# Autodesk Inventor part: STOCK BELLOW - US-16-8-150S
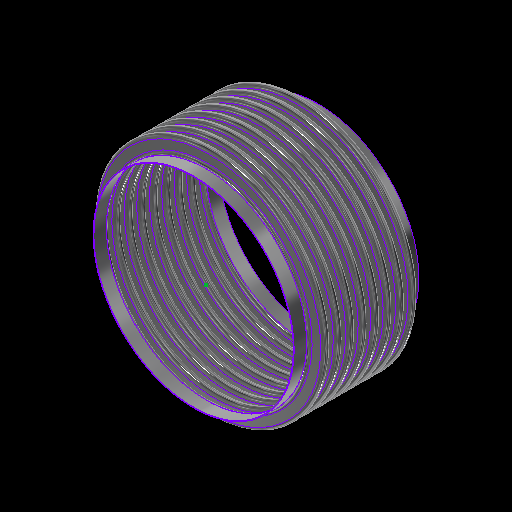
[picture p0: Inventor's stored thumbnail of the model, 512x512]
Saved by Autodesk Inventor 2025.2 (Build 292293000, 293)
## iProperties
Category: 16 GA (0.060 THICK)
RuleStatus: InUse
Created: 2024-01
Part Number: STOCK BELLOW - US-16-8-150S
Project: =STOCK BELLOWS: <Stock Number><SFILL>
Material: ASTM A240-304
Description: =STOCK BELLOWS: <Stock Number>, <SID_> I.D., <SOD_> O.D., <SPLY_> PLY, <Category>, <SNET_CONS> CONS.<PITCH_><STANGENT_> TANGENT<SFILL>
Document SubType Name: Sheet Metal
Designer: GS
Stock Number: U.S-16-8-150S
Surface Area: 17926.1 cm^2
Volume: 1357.04 cm^3
Sheet Metal Rule: Default
Appearance: STAINLESS STEEL
Mass: 10934.1 g
Density: 8.05729 g/cm^3
THK: 0.036
ID: 3.500
OD: 4.250
CONS_: 2
PITCH: 0.500
TANGENT: 0.500
BELLOWS_UPSET: 0.000
d79: 1.000
d82: 1.000
d83: 26.000
d84: 24.000
d174: 8
d214: 8
STHK_: 0.060
SID_: 16.000
SOD_: 18.500
SPITCH_: 1.000
STANGENT__: 1.000
SBELLOWS_UPSET_: 0.000
SDIFF_TAN: 1.000
d252: 2
d275: 2
d287: 0.050
d289: 0.500
d290: 0.000
SOD_NECK: 16 1/8
PLY: 1
PSET: 4.178
PBAR: 1.035
COUNTER: 1.500
NET_TUBE: 3.071
CONS: 2
S_CONS: 0
NET_CONS: 2
ID_M: 88.90 mm
OD_M: 107.95 mm
THK_M: 0.91 mm
ID_U: 3.500 in
OD_U: 4.250 in
THK_U: 0.036 in
TANGENT2: 0.500
TAN_TO_TAN: 1.000 in
d80: 2.571
d81: 10
SID: 2.375
SCONS_: 8
SPITCH: 0.250
STANGENT_: 1.000
SBELLOWS_UPSET: 0.000
SNET_CONS: 8
SS_CONS: 0
SCONS: 8
d190: 8
d191: 1
d192: 1
d193: 8
d194: 0
SIZE: 16.00
PRESSURE: 150
d230: 8
STANGENT: 4.000
SPLY_: 1
d233: 8
d234: 0
d263: 2
d265: 1
d268: 2
d269: 0
d286: 2
d288: 1
d291: 2
d292: 0
SREROLL: 0.750
BLETP: 0.000 ul
PRES_Copy: 85
MATTABLE: 20 GA (0.036 THICK)
PART_NUMBER: U.S-16-8-150S
PITCH_: =, <SPITCH_> PITCH,
CFILL: .
SFILL: .
MESH: ,
COMP: 1.52
EXT: 0.76
LAT: 0.23
ANG: 573
ASR: 4473
LSR: 28074
ANSR: 2613
PRES: 150
COMPM: 15.2
EXTM: 7.6
LATM: 2.30
ASRM: 783.356
PRESM: 10.342
LSRM: 4916.600
ANSRM: 457.615
TEMPMIN: 20
TEMPMAX: 800
TEMPMINM: -7
TEMPMAXM: 427
WEIGHTM: 10.934
WEIGHT: 24.105
Author: GS
Keywords: 20 GA (0.036 THICK)
Comments: =STOCK BELLOW - <STOCK NUMBER>
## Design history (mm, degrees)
sketch "Sketch2"
  geometry: L1 (0, -177.245)-(0, 562.856) reference; L2 (45.364, 0)-(44.45, 0); L3 (48.082, -2.718)-(50.343, -2.718); L4 (48.082, -3.632)-(50.343, -3.632); L5 (50.343, -9.982)-(48.082, -9.982); L6 (50.343, -9.068)-(48.082, -9.068); L7 (45.364, -12.7)-(44.45, -12.7); L8 (48.082, 0)-(48.082, -12.7); L9 (50.343, -6.35)-(53.975, -6.35); L10 (44.45, 0)-(44.45, -12.7); L11 (20.376, 102.841)-(20.376, 101.926); L12 (58.262, 457.127)-(58.262, 349.177); L13 (58.262, 444.427)-(58.262, 336.477); L14 (93.133, -58.817)-(93.133, -71.517); L15 (118.746, -66.401)-(118.746, -66.401); L16 (50.343, -9.068)-(50.343, -9.982); L17 (48.082, -9.068)-(48.082, -9.982); L18 (48.082, -9.525)-(50.343, -9.525); L19 (53.975, 0)-(53.975, -12.7); L20 (-50.343, -9.068)-(-50.343, -9.982); L21 (-50.343, -2.718)-(-48.082, -2.718); L22 (-50.343, -3.632)-(-48.082, -3.632); L23 (-48.082, -9.068)-(-50.343, -9.068); L24 (-50.343, -9.525)-(-48.082, -9.525); L25 (-48.082, -9.982)-(-50.343, -9.982); L26 (-48.082, -9.068)-(-48.082, -9.982); L27 (-44.45, 0.653)-(-44.45, -12.047); L28 (-48.082, -6.35)-(-44.45, -6.35); L29 (-50.343, 0.653)-(-50.343, -12.7); L30 (-53.061, 0)-(-53.975, 0); L31 (-53.975, 0)-(-53.975, -12.7); L32 (-53.061, -12.7)-(-53.975, -12.7); A1 r 2.718 centre (48.082, 0) between (45.364, 0) and (48.082, -2.718); A2 r 3.632 centre (48.082, 0) between (44.45, 0) and (48.082, -3.632); A3 r 3.632 centre (50.343, -6.35) between (50.343, -9.982) and (50.343, -2.718); A4 r 2.718 centre (50.343, -6.35) between (50.343, -9.068) and (50.343, -3.632); A5 r 2.718 centre (48.082, -12.7) between (48.082, -9.982) and (45.364, -12.7); A6 r 3.632 centre (48.082, -12.7) between (48.082, -9.068) and (44.45, -12.7); A7 r 3.175 centre (50.343, -6.35) between (50.343, -9.525) and (53.518, -6.35); A8 r 3.175 centre (48.082, -12.7) between (48.082, -9.525) and (44.907, -12.7); A9 r 2.718 centre (-50.343, -12.7) between (-50.343, -9.982) and (-53.061, -12.7); A10 r 2.718 centre (-48.082, -6.35) between (-48.082, -9.068) and (-48.082, -3.632); A11 r 3.175 centre (-48.082, -6.35) between (-48.082, -9.525) and (-44.907, -6.35); A12 r 3.632 centre (-48.082, -6.35) between (-48.082, -9.982) and (-48.082, -2.718); A13 r 3.175 centre (-50.343, -12.7) between (-50.343, -9.525) and (-53.518, -12.7); A14 r 3.632 centre (-50.343, -12.7) between (-50.343, -9.068) and (-53.975, -12.7); A15 r 2.718 centre (-50.343, 0) between (-53.061, 0) and (-50.343, -2.718); A16 r 3.632 centre (-50.343, 0) between (-53.975, 0) and (-50.343, -3.632); 10 further points
  constraints: 62 end point, 38 point on circle, 20 tangent, 16 centre point, 12 parallel, 9 midpoint, 7 vertical, 6 coincident, 6 concentric, 6 point on line, 4 equal radius, 4 perpendicular, 3 horizontal, 1 collinear, 1 horizontal alignment, 10 other
  dimensions: "THK" = 0.9144 distance of L11.start L11.end; "ID" = 88.9 distance of L11.end point (20.376, 13.026); "OD" = 107.95 distance of L12.start L12.end; "PITCH" = 12.7 distance of L12.start L13.start; "TANGENT" = 12.7 distance of L14.start L14.end; "BELLOWS_UPSET" = 0 distance of L15.start L15.end; "d43" = 88.9 diameter of L10 L1 (= ID); "d44" = 107.95 diameter of L9.end L1 (= OD); "d45" = 0.9144 distance between parallel lines of L5 L6 (computed from THK, PLY); "d46" = 3.6322 radius of A3 (computed from PITCH, THK, PLY); "UPSET_PITCH" = 12.7 distance of L2.end L7.end (derived); "SIDEWALL_ANGLE" = 360 deg dimension on L3 L9 (derived); "CON_GAP" = 5.4356 distance of point (48.082, -9.068) point (48.082, -3.632) (derived); "TAN1" = 4.98728 dimension on A8 (derived); "TAN2" = 4.98728 dimension on A7 (derived); "LEG1" = 2.2606 distance of L18.start L18.end (derived); "d278" = 0.9144 distance between parallel lines of L25 L23 (derived); "d279" = 3.6322 radius of A12 (derived); "d280" = 12.7 distance of L30.end L31.end (derived); "d281" = 360 deg dimension on L21 L28 (derived); "d282" = 5.4356 distance of point (-50.343, -9.068) point (-50.343, -3.632) (derived); "d283" = 4.98728 dimension on A13 (derived); "d284" = 4.98728 dimension on A11 (derived); "d285" = 2.2606 distance of L24.start L24.end (derived); "d293" = 88.9 diameter of L27 L1 (derived); "d294" = 107.95 diameter of L31 L1 (derived)
  node "Sketch Rectangular Pattern1" dims "d31" = 25.4, "ID" = 88.9
  node "Sketch Rectangular Pattern2" dims "d39" = 25.4, "PITCH" = 12.7
revolve "CONS" stored, may be unused: angle "d48" = 90 deg
node "BELLOW MIDPLANE"
pattern_linear "Rectangular Pattern2" dims "d52" = 12.7 (= UPSET_PITCH)
sketch "Sketch5"
  geometry: C1 r 45.364 at (0, 0) reference; C2 r 44.45 at (0, 0) reference
extrude "TANGENT" new body sketch "Sketch5" distance "d53" = 12.7 (= TANGENT); taper "d54" = 0 deg
revolve "SAMETAN" stored, may be unused: angle "d65" = 90 deg
revolve "DIFFTAN" stored, may be unused: angle "d70" = 90 deg
sketch "Sketch9"
  geometry: L1 (53.319, 0)-(-53.319, 0) reference; L2 (0, -17.78)-(0, 17.78) reference; L3 (38.085, 0)-(-38.085, 0); L4 (38.085, -11.906)-(38.085, 11.906); L5 (25.385, -11.906)-(25.385, 11.906); L6 (13.15, 11.906)-(13.15, -11.906); L7 (-25.385, -11.906)-(-25.385, 11.906); L8 (-38.085, -11.906)-(-38.085, 11.906); L9 (37.291, -11.906)-(37.291, 11.906); L10 (38.085, -11.906)-(37.291, -11.906); L11 (38.085, 11.906)-(37.291, 11.906); L12 (13.546, 11.906)-(12.753, 11.906); L13 (12.753, 11.906)-(12.753, -11.906); L14 (12.753, -11.906)-(13.546, -11.906); L15 (13.546, -11.906)-(13.546, 11.906); L16 (-13.546, 11.906)-(-13.546, -11.906); L17 (-13.15, 11.906)-(-13.15, -11.906); L18 (-13.546, -11.906)-(-12.753, -11.906); L19 (-12.753, -11.906)-(-12.753, 11.906); L20 (-12.753, 11.906)-(-13.546, 11.906); L21 (-38.085, -11.906)-(-37.291, -11.906); L22 (-37.291, -11.906)-(-37.291, 11.906); L23 (-37.291, 11.906)-(-38.085, 11.906); L24 (-38.085, 11.906)-(-38.085, -11.906); L25 (38.085, -0.397)-(-38.085, -0.397); L26 (-38.085, -0.397)-(-38.085, 0.397); L27 (-38.085, 0.397)-(38.085, 0.397); L28 (38.085, 0.397)-(38.085, -0.397); L29 (-38.085, 11.906)-(38.085, 11.906); L30 (38.085, 11.906)-(38.085, 12.7); L31 (38.085, 12.7)-(-38.085, 12.7); L32 (-38.085, 12.7)-(-38.085, 11.906); L33 (38.085, -11.906)-(-38.085, -11.906); L34 (-38.085, -11.906)-(-38.085, -12.7); L35 (-38.085, -12.7)-(38.085, -12.7); L36 (38.085, -12.7)-(38.085, -11.906); 30 further points
  constraints: 68 end point, 13 midpoint, 13 parallel, 8 horizontal, 7 perpendicular, 6 equal length, 3 point on line, 2 vertical, 14 other
  dimensions: "d115" = 23.8125 distance of L4.start L4.end (derived); "d116" = 12.7 distance between parallel lines of L4 L5 (derived); "d117" = 12.23516 distance between parallel lines of L5 L6 (derived); "d125" = 38.53427 distance between parallel lines of L7 L6 (derived); "d127" = 12.7 distance between parallel lines of L8 L7 (derived); "d128" = 24.93516 distance between parallel lines of L6 L4 (derived); "d130" = 76.16943 distance between parallel lines of L8 L4 (derived); "RULER_THK" = 0.79375 distance between parallel lines of L4 L9; "d135" = 0.79375 distance of L13.end L14.end (derived); "d138" = 26.29911 distance of L13.end L16.end (derived); "d143" = 0.79375 distance of L22.end L8.end (derived); "d144" = 0.79375 distance between parallel lines of L27 L25 (derived)
extrude "RULER" join sketch "Sketch9" distance "d149" = 0.79375 (derived); taper "d150" = 0 deg
extrude "BARS" join sketch "Sketch9" distance "d151" = 0.79375 (derived); taper "d152" = 0 deg
pattern_linear "Rectangular Pattern4" dims "d155" = 26.29911 (derived)
sketch "Sketch13"
  geometry: L1 (93.149, -52.467)-(93.149, -77.867); L2 (204.724, 0)-(203.2, 0); L3 (204.724, -25.4)-(203.2, -25.4); L4 (227.838, -19.812)-(210.312, -19.812); L5 (227.838, -18.288)-(210.312, -18.288); L6 (227.838, -12.7)-(234.95, -12.7); L7 (210.312, -5.588)-(227.838, -5.588); L8 (210.312, 0)-(210.312, -25.4); L9 (203.2, 0)-(203.2, -25.4); L10 (58.254, -26.531)-(58.254, -496.431); L11 (58.254, -51.931)-(58.254, -521.831); L12 (58.254, -102.731)-(58.254, -572.631); L13 (58.254, -128.131)-(58.254, -598.031); L14 (58.254, -153.531)-(58.254, -623.431); L15 (58.254, -178.931)-(58.254, -648.831); L16 (58.254, -204.331)-(58.254, -674.231); L17 (58.254, -77.331)-(58.254, -547.231); L18 (20.376, 103.45)-(20.376, 101.926); L19 (210.312, -7.112)-(227.838, -7.112); L20 (0, -829.767)-(0, 258.986) reference; L21 (-46.99, 0)-(281.94, 0) reference; A1 r 5.588 centre (210.312, 0) between (204.724, 0) and (210.312, -5.588); A2 r 5.588 centre (210.312, -25.4) between (210.312, -19.812) and (204.724, -25.4); A3 r 7.112 centre (210.312, -25.4) between (210.312, -18.288) and (203.2, -25.4); A4 r 5.588 centre (227.838, -12.7) between (227.838, -18.288) and (227.838, -7.112); A5 r 7.112 centre (227.838, -12.7) between (227.838, -19.812) and (227.838, -5.588); A6 r 7.112 centre (210.312, 0) between (203.2, 0) and (210.312, -7.112); 6 further points; 1 other entity
  constraints: 38 end point, 15 point on circle, 9 tangent, 6 centre point, 6 parallel, 5 vertical alignment, 4 point on line, 4 vertical, 3 coincident, 3 concentric, 2 collinear, 2 equal radius, 1 horizontal, 1 perpendicular, 23 other
  dimensions: "SBELLOWS_UPSET_" = 0 distance of point (118.762, -66.401) point (118.762, -66.401); "STOTAL_THK_BELLOW__" = 1.524 distance between parallel lines of L4 L5 (derived); "d224" = 7.112 radius of A5 (derived); "d225" = 25.4 distance of L2.end L3.end (derived); "SSIDEWALL_ANGLE_" = 360 deg dimension on L7 L6 (derived); "SSCON_GAP_" = 11.176 distance of point (210.312, -18.288) point (210.312, -7.112) (derived); "d235" = 406.4 diameter of L9 L20 (derived); "d236" = 469.9 diameter of L6.end L20 (derived)
  node "Sketch Rectangular Pattern4" dims "d228" = 25.4
  node "Sketch Rectangular Pattern5" dims "d229" = 25.4
revolve "SBELLOW" stored, may be unused: angle "d197" = 90 deg
pattern_linear "Rectangular Pattern5" dims "d204" = 25.4 (derived)
revolve "STANGENT" stored, may be unused: angle "d240" = 90 deg
revolve "SSAMETAN" stored, may be unused: angle "d241" = 90 deg
revolve "SDIFFTAN" stored, may be unused: angle "d246" = 90 deg
revolve "INVCON" stored, may be unused: angle "d295" = 90 deg
pattern_linear "Rectangular Pattern6" dims "d298" = 12.7 (derived)
revolve "INVTANGENT" stored, may be unused: angle "d302" = 90 deg
revolve "INVSAMETAN" stored, may be unused: angle "d307" = 90 deg
revolve "INVDIFFTAN" stored, may be unused: angle "d312" = 90 deg
sketch "ID BELLOW MOUNT CALC"
  geometry: L1 (44.45, 0)-(38.1, 0); L2 (38.1, 0)-(38.1, 12.7); L3 (38.1, 12.7)-(44.45, 12.7); L4 (44.45, 12.7)-(44.45, 0); L5 (36.513, 12.7)-(35.598, 12.7); L6 (35.598, 12.7)-(35.598, 0); L7 (35.598, 0)-(36.513, 0); L8 (36.513, 0)-(36.513, 12.7); L9 (0, -2.54)-(0, 15.24) reference; L10 (-8.89, 0)-(53.34, 0) reference; 1 further point
  constraints: 16 end point, 5 parallel, 2 collinear, 2 horizontal, 2 perpendicular
  dimensions: "d314" = 12.7 distance of L5.end L6.end (derived); "d315" = 0.9144 distance of L5.start L5.end (derived); "IG" = 1.5875 distance between parallel lines of L2 L8; "PIPE_OD" = 88.9 diameter of L4 L9; "PIPE_WALL" = 6.35 distance of L2.end L3.end; "ID_MT_BELLOW" = 71.1962 diameter of L6 L9 (derived)
revolve "CFILL" stored, may be unused: angle "d320" = 90 deg
pattern_linear "Rectangular Pattern7" dims "d323" = 12.7 (derived)
revolve "SFILL" stored, may be unused: angle "d324" = 90 deg
pattern_linear "Rectangular Pattern8" dims "d327" = 25.4 (derived)
node "STOCK BELLOW MIDPLANE"
node "BELLOW"
sketch "Sketch6"
  geometry: L1 (-12.7, 45.364)-(0, 45.364); L2 (0, 45.364)-(0, 44.45); L3 (0, 44.45)-(-12.7, 44.45); L4 (-12.7, 44.45)-(-12.7, 45.364); L5 (10.16, 0)-(-60.96, 0) reference; L6 (-38.1, -89.422)-(-38.1, 153.44) reference; 1 further point
  constraints: 8 end point, 2 parallel, 1 horizontal, 1 perpendicular
  dimensions: "d61" = 12.7 distance of L2.end L3.end (derived); "d62" = 0.9144 distance of L1.end L2.end (derived); "d63" = 88.9 diameter of L3 L5 (derived); "d64" = 25.4 distance between parallel lines of L4 L6 (derived)
sketch "Sketch12"
  geometry: 1 further point
sketch "Sketch14"
  geometry: L1 (-25.4, 204.724)-(0, 204.724); L2 (0, 204.724)-(0, 203.2); L3 (0, 203.2)-(-25.4, 203.2); L4 (-25.4, 203.2)-(-25.4, 204.724); L5 (5.08, 0)-(-30.48, 0) reference; L6 (0, -40.945)-(0, 245.669) reference; 1 further point
  constraints: 8 end point, 2 parallel, 1 collinear, 1 horizontal, 1 perpendicular
  dimensions: "d237" = 1.524 distance of L3.end L1.start (derived); "d238" = 406.4 diameter of L3 L5 (derived); "d239" = 25.4 distance of L1.start L1.end (derived); "SOD_NECK" = 409.448 diameter of L1 L5 (derived)
sketch "Sketch15"
  geometry: L1 (-40.945, 0)-(245.669, 0) reference; L2 (203.2, -203.2)-(204.724, -203.2); L3 (204.724, -203.2)-(204.724, -228.6); L4 (204.724, -228.6)-(203.2, -228.6); L5 (203.2, -228.6)-(203.2, -203.2); L6 (0, -276.86)-(0, 60.96) reference; 1 further point
  constraints: 8 end point, 2 parallel, 1 horizontal, 1 perpendicular
  dimensions: "d205" = 25.4 distance of L4.end L2.start (derived); "d206" = 1.524 distance of L3.end L4.end (derived); "d207" = 406.4 diameter of L5 L6 (derived); "d208" = 203.2 distance between parallel lines of L1 L2 (derived)
node "TANGENT_"
node "SAME_TAN"
sketch "Sketch8"
  geometry: L1 (45.364, -25.4)-(44.45, -25.4); L2 (44.45, -25.4)-(44.45, -38.1); L3 (44.45, -38.1)-(45.364, -38.1); L4 (45.364, -38.1)-(45.364, -25.4); L5 (0, -48.26)-(0, 22.86) reference; L6 (-89.422, 0)-(153.44, 0) reference; 1 further point
  constraints: 8 end point, 2 parallel, 1 horizontal, 1 perpendicular
  dimensions: "d66" = 88.9 diameter of L2 L5 (derived); "TOTAL_THK_BELLOW" = 0.9144 distance of L2.end L3.end (derived); "d68" = 25.4 distance between parallel lines of L1 L6 (derived); "d69" = 12.7 distance of L1.end L2.end (derived)
node "DIFF_TAN"
node "Sketch Rectangular Pattern3" dims "d138" = 26.29911 (derived), "d141" = 25.4
node "SBELLOW_"
node "STANGENT_"
node "SSAME_TAN"
sketch "Sketch16"
  geometry: L1 (204.724, -203.2)-(203.2, -203.2); L2 (203.2, -203.2)-(203.2, -228.6); L3 (203.2, -228.6)-(204.724, -228.6); L4 (204.724, -228.6)-(204.724, -203.2); L5 (0, -276.86)-(0, 60.96) reference; L6 (-40.945, 0)-(245.669, 0) reference; 1 further point
  constraints: 8 end point, 2 parallel, 1 horizontal, 1 perpendicular
  dimensions: "SDIFF_TAN" = 25.4 distance of L3.end L1.start; "d243" = 1.524 distance of L2.end L3.end (derived); "d244" = 203.2 distance between parallel lines of L1 L6 (derived); "d245" = 406.4 diameter of L2 L5 (derived)
node "SDIFF_TAN"
body "Solid15"
sketch "Sketch17"
  geometry: L1 (53.975, 12.7)-(53.061, 12.7); L2 (53.061, 12.7)-(53.061, 0); L3 (53.061, 0)-(53.975, 0); L4 (53.975, 0)-(53.975, 12.7); L5 (0, -2.54)-(0, 15.24) reference; L6 (-10.795, 0)-(64.77, 0) reference; 2 further points
  constraints: 8 end point, 2 parallel, 1 horizontal, 1 midpoint, 1 perpendicular, 1 point on line
  dimensions: "INVTANGENT" = 12.7 distance of L3.end L1.start (derived); "d300" = 0.9144 distance of L1.start L1.end (derived); "d301" = 107.95 diameter of L4 L5 (derived)
body "Solid16"
sketch "Sketch18"
  geometry: L1 (53.975, -25.4)-(53.061, -25.4); L2 (53.061, -25.4)-(53.061, -38.1); L3 (53.061, -38.1)-(53.975, -38.1); L4 (53.975, -38.1)-(53.975, -25.4); L5 (-10.795, 0)-(64.77, 0) reference; L6 (0, -48.26)-(0, 22.86) reference; 1 further point
  constraints: 8 end point, 2 parallel, 1 horizontal, 1 perpendicular
  dimensions: "d303" = 25.4 distance between parallel lines of L1 L5 (derived); "d304" = 12.7 distance of L3.end L1.start (derived); "d305" = 0.9144 distance of L2.end L3.end (derived); "d306" = 107.95 diameter of L4 L6 (derived)
body "Solid17"
sketch "Sketch19"
  geometry: L1 (53.975, -25.4)-(53.061, -25.4); L2 (53.061, -25.4)-(53.061, -38.1); L3 (53.061, -38.1)-(53.975, -38.1); L4 (53.975, -38.1)-(53.975, -25.4); L5 (0, -48.26)-(0, 22.86) reference; L6 (-10.795, 0)-(64.77, 0) reference; 1 further point
  constraints: 8 end point, 2 parallel, 1 horizontal, 1 perpendicular
  dimensions: "d308" = 12.7 distance of L1.end L2.end (derived); "d309" = 107.95 diameter of L4 L5 (derived); "d310" = 0.9144 distance of L2.end L3.end (derived); "d311" = 25.4 distance between parallel lines of L1 L6 (derived)
body "Solid18"
body "Solid19"
body "Solid20"
other parameters: "BMPL" = -101.6, "PSET" = 106.1212 (computed from OD, THK, PLY) [user parameter], "PBAR" = 26.29911 (= 0.570796 x PITCH + OD - ID) [user parameter; used in 1 equation term], "COUNTER" = 15 [user parameter], "NET_TUBE" = 77.99823 (computed from CONS_, PBAR, TANGENT) [user parameter], "S_CONS" = 0 [user parameter; used in 1 equation term], "ID_M" = 88.9 (= ID) [user parameter], "OD_M" = 107.95 (= OD) [user parameter], "THK_M" = 0.9144 (= THK) [user parameter], "ID_U" = 88.9 (= ID) [user parameter], "OD_U" = 107.95 (= OD) [user parameter], "THK_U" = 0.9144 (= THK) [user parameter], "D_UNITS" = 0 [user parameter], "TANGENT2" = 12.7 [user parameter], "TAN_TO_TAN" = 25.4 [user parameter], "OD_NECK" = 90.7288 [user parameter], "d79" = 25.4, "d80" = 65.29823 [user parameter], "d82" = 25.4, "d83" = 660.4, "d84" = 609.6, "sa_0" = 4, "FRAME_THK" = 0.79375 [user parameter], "CON_FLAT" = 12.23516 [user parameter], "SID" = 60.325 [user parameter], "SPITCH" = 6.35 [user parameter], "STANGENT_" = 25.4 [user parameter], "SBELLOWS_UPSET" = 0 [user parameter], "SS_CONS" = 0 [user parameter], "STAN_TO_TAN_" = 203.2 [user parameter], "d100" = 1.524 [user parameter], "d191" = 25.4 [user parameter], "d194" = 0 [user parameter], "STANGENT" = 101.6 [user parameter], "d234" = 0 [user parameter], "SUPSET_PITCH_" = 25.4 [user parameter], "d269" = 0 [user parameter], "d287" = 1.27, "d289" = 12.7, "d290" = 0, "d292" = 0 [user parameter], "Thickness" = 3.048 (derived), "KFactor" = 4.4, "BendRadius" = 3.048 (derived), "BendReliefWidth" = 3.048 (derived), "BendReliefDepth" = 1.524 (derived), "CornerReliefSize" = 12.192 (derived), "SeamGap" = 0.00508, "MinimumRemnant" = 6.096 (derived), "TransitionRadius" = 3.048 (derived), "JacobiRadiusSize" = 3.048 (derived), "GapSize" = 3.048 (derived), "SREROLL" = 19.05 [user parameter], "CUR_STK_PITCH" = 25.4 [user parameter], "d328" = -101.6 (derived), "ASR" = 44730 [user parameter], "LSR" = 280740 [user parameter], "ANSR" = 26130 [user parameter], "BLETP" = 0 [user parameter], "ASRM" = 7833.5649 [user parameter], "PRESM" = 103.41975 [user parameter], "LSRM" = 49165.9962 [user parameter], "ANSRM" = 4576.1469 [user parameter], "TEMPMIN" = 2664.83333 [user parameter], "TEMPMAX" = 6998.16667 [user parameter], "TEMPMINM" = 2664.83333 [user parameter], "TEMPMAXM" = 6998.16667 [user parameter], "WEIGHT" = 109.3407 [user parameter], "WEIGHTM" = 0.10934 [user parameter]
